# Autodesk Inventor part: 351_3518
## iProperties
Author: tomm
Created: 2002-01
Part Number: 351_3518
Document SubType Name: Modeling
Designer: tomm
Material: Steel, Mild
Control State: 0
Master: False
Checked Out: False
Last Check In Date: 2002-01-29
PropertySet Name: Design Tracking Control
Last Check In By: tomm
Shininess: 25.0
PropertySet Name: _Private Model Information
Density: 7.86
Volume: 2.6461258136751376
Area: 11.164330162393595
PropertySet Name: Model Information
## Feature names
1. Extrusion1
2. Chamfer1
3. Extrusion2
4. Base1
